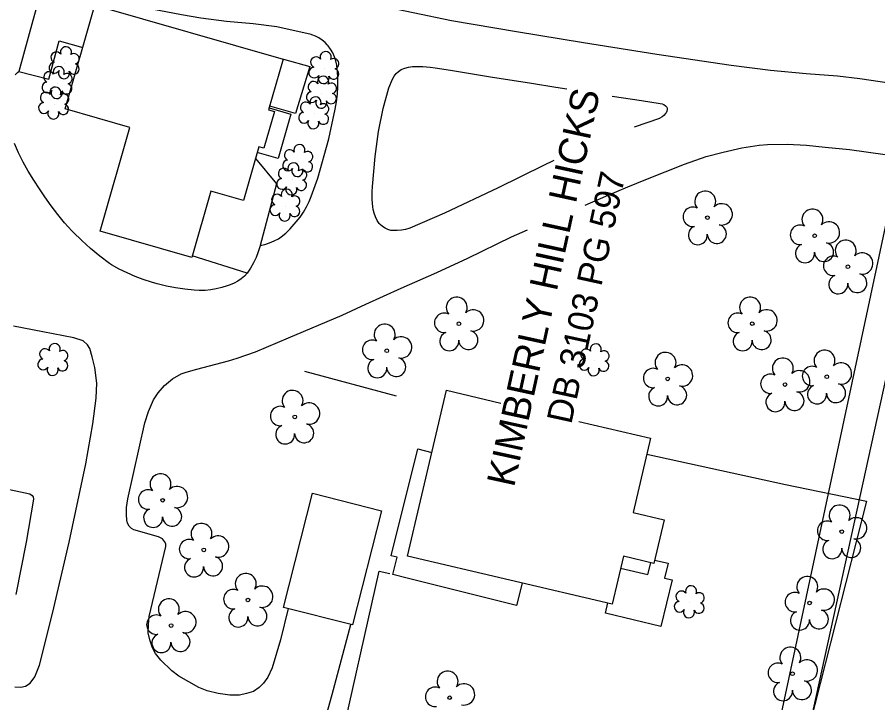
# Model space of a CAD drawing. Extents: x 1611576 to 1617186, y 899279 to 905462.
# Drawn here: x 1616359.3 to 1616512.4, y 901237.8 to 901359.7 of the extents above; entities that cross this region are included whole.
import ezdxf

# ---------------------------------------------------------------- set-up
doc = ezdxf.new("R2010")
doc.units = 0
for name, color, linetype in [('Exist Building', 7, 'Continuous'), ('Exist Building Metal Canopy', 7, 'Continuous'), ('Exist Other Culture Area Outline', 7, 'Continuous'), ('Exist Other Culture Fence Line', 7, 'Continuous'), ('Exist Property Deed Book Text', 7, 'Continuous'), ('Exist Property Owner Text', 7, 'Continuous'), ('Exist Roads Soil', 7, 'Continuous'), ('Exist Vegetation Shrub CELL', 7, 'Continuous'), ('Exist Vegetation Tree CELL', 7, 'Continuous'), ('Prop 6 In Gas Line (B2)', 7, 'Continuous'), ('Prop OH Pow Tel CATV Lines', 7, 'Continuous')]:
    doc.layers.add(name, color=color, linetype=linetype)

msp = doc.modelspace()

# ---------------------------------------------------------------- linework, layer by layer
at = {"layer": 'Exist Building'}
msp.add_lwpolyline([(1616367.84, 901343.41), (1616373.15, 901361.89), (1616406.65, 901352.27), (1616404.06, 901343.26), (1616405.09, 901342.96), (1616403.21, 901336.42), (1616402.31, 901336.68), (1616399.57, 901327.14), (1616393.78, 901328.81), (1616390.39, 901317), (1616374.07, 901321.69), (1616379.36, 901340.1)], close=True, dxfattribs=at)
msp.add_lwpolyline([(1616459.25, 901287.84), (1616472.01, 901284.86), (1616468.9, 901271.6), (1616474.4, 901270.32), (1616472.58, 901262.57), (1616467.17, 901263.84), (1616465.19, 901255.34), (1616428.78, 901263.86), (1616435.68, 901293.36), (1616445.35, 901291.1)], dxfattribs=at)
at = {"layer": 'Exist Building Metal Canopy'}
msp.add_lwpolyline([(1616424.14, 901271.94), (1616419, 901251.63), (1616406.73, 901254.74), (1616411.87, 901275.05)], close=True, dxfattribs=at)
at = {"layer": 'Exist Other Culture Area Outline'}
for points in [[(1616374.23, 901361.58), (1616374.63, 901362.94), (1616374.66, 901363.02), (1616369.34, 901364.47), (1616364, 901365.94), (1616362.13, 901359.12), (1616359.6, 901350.09), (1616364.93, 901348.68), (1616366.82, 901355.52), (1616370.98, 901354.34)], [(1616406.69, 901352.27), (1616411.36, 901350.93), (1616408.86, 901342.62), (1616404.25, 901343.93)], [(1616404.15, 901343.58), (1616408, 901342.49), (1616405.75, 901334.6), (1616402.02, 901335.66)], [(1616401.71, 901334.58), (1616405.43, 901330.11), (1616402.56, 901319.1), (1616402.54, 901319.04), (1616402.22, 901318), (1616401.83, 901316.99), (1616401.36, 901316.01), (1616400.82, 901315.06), (1616400.25, 901314.21), (1616390.46, 901317.25)], [(1616449.19, 901259.08), (1616448.18, 901255.06), (1616428.71, 901259.95), (1616426.16, 901260.6), (1616426.92, 901263.65), (1616425.84, 901263.92), (1616430.62, 901282.94), (1616433.09, 901282.31)], [(1616472.72, 901263.17), (1616475.12, 901262.59), (1616474.49, 901259.95), (1616475.82, 901259.63), (1616473.85, 901251.35), (1616463.96, 901253.71), (1616464.39, 901255.53)], [(1616466.68, 901261.73), (1616471.52, 901260.58), (1616472.03, 901262.7)]]:
    msp.add_lwpolyline(points, dxfattribs=at)
at = {"layer": 'Exist Other Culture Fence Line'}
msp.add_line((1616426.82, 901292.33), (1616410.48, 901296.69), dxfattribs=at)
msp.add_lwpolyline([(1616471.34, 901282), (1616496, 901276.61), (1616510.44, 901273.65), (1616499.39, 901230.25), (1616492.71, 901200.51), (1616464, 901211.34), (1616431.25, 901223.21), (1616416.45, 901228.69), (1616423.75, 901261.2), (1616425.59, 901260.77)], dxfattribs=at)
at = {"layer": 'Exist Roads Soil'}
for points in [[(1616414.1, 901355.23), (1616413.58, 901355.67), (1616413.01, 901356.05), (1616412.39, 901356.37), (1616411.75, 901356.6), (1616411.62, 901356.64), (1616405.52, 901358), (1616401.33, 901358.52), (1616396.57, 901358.97), (1616392.02, 901359.55), (1616388.53, 901360.13), (1616383.27, 901361.16), (1616374.66, 901363.02)], [(1616523.33, 901346.48), (1616519.44, 901347.01), (1616514.46, 901347.97), (1616509.21, 901348.79), (1616505.25, 901349.23), (1616499.66, 901349.68), (1616493.34, 901350.26), (1616486.34, 901351.16), (1616473.14, 901353.09), (1616460.08, 901355.19), (1616448.14, 901357.11), (1616436.59, 901359.1), (1616422.94, 901361.95)], [(1616402.56, 901319.1), (1616403.41, 901319.3), (1616404.24, 901319.57), (1616405.05, 901319.92), (1616405.82, 901320.33), (1616406.27, 901320.63), (1616407.11, 901321.32), (1616407.9, 901322.08), (1616408.63, 901322.89), (1616408.96, 901323.31), (1616409.64, 901324.15), (1616410.25, 901325.04), (1616410.79, 901325.98), (1616411.26, 901326.95), (1616411.61, 901327.82), (1616412.8, 901331.1), (1616414.78, 901338.12), (1616415.88, 901343.34), (1616416.12, 901344.69), (1616416.28, 901346.06), (1616416.36, 901347.43), (1616416.36, 901348.8), (1616416.28, 901350.17), (1616416.25, 901350.47), (1616416.17, 901351.22), (1616416.01, 901351.96), (1616415.77, 901352.68), (1616415.46, 901353.37), (1616415.07, 901354.02), (1616414.63, 901354.63), (1616414.47, 901354.82), (1616414.1, 901355.23)], [(1616358.96, 901349.45), (1616359.41, 901349.92), (1616359.6, 901350.09)], [(1616454.8, 901334.26), (1616452.93, 901333.37), (1616444.91, 901329.39), (1616435.34, 901324.88), (1616429.16, 901322.21), (1616428.43, 901321.98), (1616427.69, 901321.84), (1616426.94, 901321.77), (1616426.18, 901321.78), (1616425.81, 901321.81), (1616425.29, 901321.96), (1616424.79, 901322.19), (1616424.33, 901322.48), (1616423.92, 901322.84), (1616423.75, 901323.03), (1616423.37, 901323.59), (1616423.06, 901324.2), (1616422.82, 901324.84), (1616422.66, 901325.5), (1616422.59, 901325.99), (1616422.5, 901327.31), (1616422.49, 901328.64), (1616422.53, 901329.59), (1616423.01, 901334.96), (1616423.59, 901339.4), (1616424.42, 901343.5), (1616425.44, 901347.16), (1616426.07, 901348.73), (1616426.37, 901349.23), (1616426.74, 901349.69), (1616427.17, 901350.09), (1616427.65, 901350.43), (1616427.66, 901350.43), (1616428.3, 901350.68), (1616428.96, 901350.85), (1616429.63, 901350.94), (1616430.16, 901350.95), (1616431.47, 901350.94), (1616432.78, 901350.84), (1616433.69, 901350.74), (1616436.39, 901350.3), (1616443.55, 901349.11), (1616450.81, 901347.99), (1616455.14, 901347.3), (1616457.08, 901346.99)], [(1616465.2, 901345.71), (1616470.38, 901344.91), (1616473.74, 901344.37), (1616474.08, 901344.31), (1616474.39, 901344.17), (1616474.66, 901343.96), (1616474.88, 901343.7), (1616474.94, 901343.61), (1616474.96, 901343.31), (1616474.91, 901343.01), (1616474.78, 901342.74), (1616474.65, 901342.57), (1616474.38, 901342.24), (1616474.05, 901341.98), (1616473.68, 901341.77), (1616473.57, 901341.73), (1616469.1, 901340.19)], [(1616400.25, 901314.21), (1616399.74, 901313.67), (1616399.18, 901313.18), (1616398.57, 901312.76), (1616397.91, 901312.4), (1616397.23, 901312.12), (1616396.69, 901311.95), (1616395.73, 901311.63), (1616394.74, 901311.38), (1616393.75, 901311.22), (1616392.74, 901311.13), (1616391.72, 901311.11), (1616390.82, 901311.17), (1616389.16, 901311.34), (1616387.5, 901311.58), (1616385.86, 901311.91), (1616384.23, 901312.31), (1616383.25, 901312.59), (1616381.76, 901313.06), (1616380.3, 901313.61), (1616378.87, 901314.23), (1616377.47, 901314.92), (1616376.11, 901315.69), (1616375.72, 901315.92), (1616374.03, 901317.23), (1616372.39, 901318.6), (1616370.81, 901320.02), (1616369.28, 901321.51), (1616369.06, 901321.73), (1616367.77, 901323.16), (1616366.54, 901324.64), (1616365.37, 901326.17), (1616364.26, 901327.75), (1616363.31, 901329.22), (1616362.27, 901330.76), (1616361.3, 901332.33), (1616360.4, 901333.95), (1616359.57, 901335.61), (1616358.82, 901337.28)], [(1616460.38, 901326.31), (1616464.07, 901327.91), (1616467.97, 901329.54), (1616471.15, 901330.85), (1616474.63, 901332.24), (1616478.05, 901333.56), (1616481.89, 901334.93), (1616484.93, 901335.73), (1616488.23, 901336.48), (1616491.34, 901336.98), (1616492.83, 901337.1), (1616496.3, 901337.13), (1616499.77, 901336.95), (1616503.08, 901336.62), (1616507.42, 901336.19), (1616513.71, 901335.32), (1616521.24, 901334.36), (1616526.1, 901333.58), (1616527.83, 901333.25)], [(1616407.54, 901254.53), (1616406.15, 901248.98), (1616404.67, 901244.01), (1616403.89, 901242.32), (1616403.13, 901241.28), (1616402.36, 901240.47), (1616401.37, 901239.8), (1616400.1, 901239.4), (1616398.85, 901239.14), (1616397.16, 901239.14), (1616395.1, 901239.4), (1616393.13, 901239.91), (1616391.62, 901240.5), (1616388.1, 901242.5), (1616386.83, 901243.43), (1616384.87, 901245.36), (1616383.96, 901246.53), (1616383.38, 901247.55), (1616382.91, 901248.99), (1616382.65, 901250.24), (1616382.69, 901251.63), (1616382.8, 901253.12), (1616385.79, 901265.58), (1616385.78, 901266.04), (1616385.55, 901266.44), (1616385.19, 901266.95), (1616384.44, 901267.32), (1616380.1, 901268.57), (1616379.68, 901268.76), (1616379.25, 901269.21), (1616378.95, 901269.73), (1616378.81, 901270.25), (1616378.76, 901271.27), (1616378.8, 901272.52), (1616379, 901274.04), (1616382.01, 901287.55), (1616382.67, 901289.61), (1616383.58, 901291.65), (1616384.38, 901292.9), (1616385.54, 901294.22), (1616386.93, 901295.41), (1616388.47, 901296.27), (1616389.38, 901296.61), (1616391.3, 901297.13), (1616396.9, 901298.58), (1616398.49, 901299.09), (1616401.73, 901300.22), (1616407.58, 901302.67), (1616417.13, 901306.74), (1616421.36, 901308.68), (1616427.64, 901311.52), (1616434.01, 901314.31), (1616439.51, 901316.87), (1616447.26, 901320.66), (1616450.1, 901321.88)], [(1616358.9, 901240.59), (1616359.98, 901240.58), (1616360.8, 901240.75), (1616361.61, 901241.29), (1616362.45, 901242.4), (1616363.31, 901244.47), (1616365.63, 901253.68), (1616368.57, 901266.32), (1616371.53, 901280.27), (1616372.78, 901287.41), (1616373.39, 901291.98), (1616373.48, 901294.61), (1616373.12, 901297.4), (1616372.69, 901299.29), (1616372.26, 901300.78), (1616371.83, 901301.47), (1616371.07, 901302.14), (1616369.38, 901302.71), (1616363.86, 901303.77), (1616358.67, 901304.74)], [(1616356.26, 901276.1), (1616361.56, 901274.96), (1616362.01, 901274.64), (1616362.17, 901274.39), (1616362.24, 901273.97), (1616360.9, 901266.34), (1616359.06, 901257.05)], [(1616414.12, 901215.18), (1616412.83, 901217.9), (1616412.15, 901219.81), (1616411.78, 901221.85), (1616411.63, 901223.98), (1616411.68, 901225.43), (1616412.07, 901227.54), (1616415.38, 901239.26), (1616418.68, 901251.71)]]:
    msp.add_lwpolyline(points, dxfattribs=at)
at = {"layer": 'Exist Vegetation Shrub CELL'}
for p, q in [((1616367.77, 901351.45), (1616367.77, 901351.45)), ((1616413.97, 901350.58), (1616413.97, 901350.58)), ((1616366.49, 901347.93), (1616366.49, 901347.93)), ((1616413.53, 901346.2), (1616413.53, 901346.2)), ((1616365.89, 901344.28), (1616365.89, 901344.28)), ((1616412.16, 901342.54), (1616412.16, 901342.54)), ((1616409.31, 901334.05), (1616409.31, 901334.05)), ((1616408.24, 901330.78), (1616408.24, 901330.78)), ((1616407.04, 901326.13), (1616407.04, 901326.13)), ((1616365.76, 901298.66), (1616365.76, 901298.66)), ((1616462.03, 901298.6), (1616462.03, 901298.6)), ((1616478.97, 901255.56), (1616478.97, 901255.56))]:
    msp.add_line(p, q, dxfattribs=at)
for centre, radius, start, end in [((1616366.29, 901352.58), 0.968, 35.8908, 245.4216), ((1616368, 901353.49), 0.99, 334.8391, 200.4717), ((1616369.44, 901352.32), 0.929, 284.4567, 126.0861), ((1616414.2, 901352.62), 0.99, 334.8391, 200.4717), ((1616365.97, 901350.75), 0.955, 95.1099, 327.9534), ((1616412.49, 901351.71), 0.968, 35.8908, 245.4216), ((1616415.64, 901351.45), 0.929, 284.4567, 126.0861), ((1616365.01, 901349.05), 0.968, 35.8908, 245.4216), ((1616366.72, 901349.97), 0.99, 334.8391, 200.4717), ((1616367.64, 901349.77), 0.984, 151.2797, 21.387), ((1616369.41, 901350.52), 0.937, 204.9913, 73.4601), ((1616412.17, 901349.88), 0.955, 95.1099, 327.9534), ((1616415.61, 901349.65), 0.937, 204.9913, 73.4601), ((1616368.16, 901348.8), 0.929, 284.4567, 126.0861), ((1616413.76, 901348.24), 0.99, 334.8391, 200.4717), ((1616413.84, 901348.9), 0.984, 151.2797, 21.387), ((1616364.69, 901347.22), 0.955, 95.1099, 327.9534), ((1616366.12, 901346.32), 0.99, 334.8391, 200.4717), ((1616368.13, 901347), 0.937, 204.9913, 73.4601), ((1616412.05, 901347.33), 0.968, 35.8908, 245.4216), ((1616415.21, 901347.07), 0.929, 284.4567, 126.0861), ((1616364.41, 901345.41), 0.968, 35.8908, 245.4216), ((1616366.36, 901346.24), 0.984, 151.2797, 21.387), ((1616367.57, 901345.15), 0.929, 284.4567, 126.0861), ((1616411.73, 901345.5), 0.955, 95.1099, 327.9534), ((1616412.39, 901344.58), 0.99, 334.8391, 200.4717), ((1616415.17, 901345.27), 0.937, 204.9913, 73.4601), ((1616364.09, 901343.58), 0.955, 95.1099, 327.9534), ((1616367.53, 901343.35), 0.937, 204.9913, 73.4601), ((1616410.68, 901343.67), 0.968, 35.8908, 245.4216), ((1616413.41, 901344.52), 0.984, 151.2797, 21.387), ((1616413.83, 901343.41), 0.929, 284.4567, 126.0861), ((1616365.77, 901342.6), 0.984, 151.2797, 21.387), ((1616410.36, 901341.84), 0.955, 95.1099, 327.9534), ((1616413.8, 901341.61), 0.937, 204.9913, 73.4601), ((1616412.03, 901340.86), 0.984, 151.2797, 21.387), ((1616409.54, 901336.09), 0.99, 334.8391, 200.4717), ((1616407.83, 901335.18), 0.968, 35.8908, 245.4216), ((1616410.98, 901334.92), 0.929, 284.4567, 126.0861), ((1616407.51, 901333.35), 0.955, 95.1099, 327.9534), ((1616408.47, 901332.82), 0.99, 334.8391, 200.4717), ((1616410.95, 901333.12), 0.937, 204.9913, 73.4601), ((1616406.75, 901331.91), 0.968, 35.8908, 245.4216), ((1616409.18, 901332.37), 0.984, 151.2797, 21.387), ((1616409.91, 901331.65), 0.929, 284.4567, 126.0861), ((1616406.44, 901330.07), 0.955, 95.1099, 327.9534), ((1616409.87, 901329.85), 0.937, 204.9913, 73.4601), ((1616407.27, 901328.17), 0.99, 334.8391, 200.4717), ((1616408.11, 901329.09), 0.984, 151.2797, 21.387), ((1616405.56, 901327.26), 0.968, 35.8908, 245.4216), ((1616408.71, 901327), 0.929, 284.4567, 126.0861), ((1616405.24, 901325.43), 0.955, 95.1099, 327.9534), ((1616408.68, 901325.2), 0.937, 204.9913, 73.4601), ((1616406.91, 901324.45), 0.984, 151.2797, 21.387), ((1616365.99, 901300.7), 0.99, 334.8391, 200.4717), ((1616462.26, 901300.64), 0.99, 334.8391, 200.4717), ((1616364.28, 901299.79), 0.968, 35.8908, 245.4216), ((1616367.43, 901299.53), 0.929, 284.4567, 126.0861), ((1616460.54, 901299.73), 0.968, 35.8908, 245.4216), ((1616463.7, 901299.47), 0.929, 284.4567, 126.0861), ((1616363.96, 901297.96), 0.955, 95.1099, 327.9534), ((1616367.4, 901297.74), 0.937, 204.9913, 73.4601), ((1616460.23, 901297.9), 0.955, 95.1099, 327.9534), ((1616463.66, 901297.67), 0.937, 204.9913, 73.4601), ((1616365.63, 901296.98), 0.984, 151.2797, 21.387), ((1616461.9, 901296.92), 0.984, 151.2797, 21.387), ((1616479.2, 901257.6), 0.99, 334.8391, 200.4717), ((1616477.48, 901256.69), 0.968, 35.8908, 245.4216), ((1616480.64, 901256.43), 0.929, 284.4567, 126.0861), ((1616477.17, 901254.86), 0.955, 95.1099, 327.9534), ((1616480.6, 901254.63), 0.937, 204.9913, 73.4601), ((1616478.84, 901253.88), 0.984, 151.2797, 21.387)]:
    msp.add_arc(centre, radius, start, end, dxfattribs=at)
at = {"layer": 'Exist Vegetation Tree CELL'}
for p, q in [((1616482.11, 901324.07), (1616482.11, 901324.07)), ((1616501.19, 901320.85), (1616501.19, 901320.85)), ((1616507.11, 901315.33), (1616507.11, 901315.33)), ((1616437.9, 901305.2), (1616437.9, 901305.2)), ((1616490.09, 901305.21), (1616490.09, 901305.21)), ((1616425.08, 901300.4), (1616425.08, 901300.4)), ((1616475.05, 901295.39), (1616475.05, 901295.39)), ((1616503.34, 901295.76), (1616503.34, 901295.76)), ((1616495.92, 901294.37), (1616495.92, 901294.37)), ((1616408.7, 901288.62), (1616408.7, 901288.62)), ((1616385.21, 901273.79), (1616385.21, 901273.79)), ((1616506.02, 901268.22), (1616506.02, 901268.22)), ((1616392.51, 901264.97), (1616392.51, 901264.97)), ((1616400.37, 901256.06), (1616400.37, 901256.06)), ((1616500.28, 901255.53), (1616500.28, 901255.53)), ((1616386.7, 901251.51), (1616386.7, 901251.51)), ((1616497.26, 901242.94), (1616497.26, 901242.94)), ((1616436.27, 901238.68), (1616436.27, 901238.68))]:
    msp.add_line(p, q, dxfattribs=at)
for centre in [(1616482.11, 901324.07), (1616501.19, 901320.85), (1616507.11, 901315.33), (1616437.9, 901305.2), (1616490.09, 901305.21), (1616425.08, 901300.4), (1616475.05, 901295.39), (1616503.34, 901295.76), (1616495.92, 901294.37), (1616408.7, 901288.62), (1616385.21, 901273.79), (1616506.02, 901268.22), (1616392.51, 901264.97), (1616400.37, 901256.06), (1616500.28, 901255.53), (1616386.7, 901251.51), (1616497.26, 901242.94), (1616436.27, 901238.68)]:
    msp.add_circle(centre, 0.326, dxfattribs=at)
for centre, radius, start, end in [((1616481.73, 901326.95), 1.86, 330.1651, 219.7134), ((1616479.51, 901324.23), 1.73, 62.6636, 279.3457), ((1616484.66, 901324.66), 1.9, 257.1011, 134.1999), ((1616500.8, 901323.73), 1.86, 330.1651, 219.7134), ((1616480.41, 901320.95), 1.69, 111.5671, 6.231), ((1616483.79, 901321.17), 1.7, 181.2822, 74.56), ((1616498.58, 901321.01), 1.73, 62.6636, 279.3457), ((1616503.74, 901321.44), 1.9, 257.1011, 134.1999), ((1616502.86, 901317.95), 1.7, 181.2822, 74.56), ((1616506.72, 901318.21), 1.86, 330.1651, 219.7134), ((1616499.48, 901317.73), 1.69, 111.5671, 6.231), ((1616504.5, 901315.49), 1.73, 62.6636, 279.3457), ((1616509.65, 901315.92), 1.9, 257.1011, 134.1999), ((1616505.4, 901312.21), 1.69, 111.5671, 6.231), ((1616508.78, 901312.43), 1.7, 181.2822, 74.56), ((1616437.52, 901308.08), 1.86, 330.1651, 219.7134), ((1616489.71, 901308.08), 1.86, 330.1651, 219.7134), ((1616440.45, 901305.79), 1.9, 257.1011, 134.1999), ((1616492.64, 901305.8), 1.9, 257.1011, 134.1999), ((1616435.3, 901305.36), 1.73, 62.6636, 279.3457), ((1616487.49, 901305.36), 1.73, 62.6636, 279.3457), ((1616424.7, 901303.28), 1.86, 330.1651, 219.7134), ((1616427.63, 901300.99), 1.9, 257.1011, 134.1999), ((1616436.2, 901302.08), 1.69, 111.5671, 6.231), ((1616439.58, 901302.3), 1.7, 181.2822, 74.56), ((1616488.39, 901302.09), 1.69, 111.5671, 6.231), ((1616491.76, 901302.31), 1.7, 181.2822, 74.56), ((1616422.48, 901300.56), 1.73, 62.6636, 279.3457), ((1616474.67, 901298.26), 1.86, 330.1651, 219.7134), ((1616502.95, 901298.63), 1.86, 330.1651, 219.7134), ((1616423.38, 901297.28), 1.69, 111.5671, 6.231), ((1616426.75, 901297.5), 1.7, 181.2822, 74.56), ((1616495.54, 901297.25), 1.86, 330.1651, 219.7134), ((1616505.88, 901296.35), 1.9, 257.1011, 134.1999), ((1616472.45, 901295.54), 1.73, 62.6636, 279.3457), ((1616477.6, 901295.98), 1.9, 257.1011, 134.1999), ((1616498.47, 901294.96), 1.9, 257.1011, 134.1999), ((1616500.73, 901295.91), 1.73, 62.6636, 279.3457), ((1616493.32, 901294.53), 1.73, 62.6636, 279.3457), ((1616408.32, 901291.5), 1.86, 330.1651, 219.7134), ((1616473.35, 901292.27), 1.69, 111.5671, 6.231), ((1616476.73, 901292.49), 1.7, 181.2822, 74.56), ((1616501.63, 901292.64), 1.69, 111.5671, 6.231), ((1616505.01, 901292.86), 1.7, 181.2822, 74.56), ((1616494.22, 901291.25), 1.69, 111.5671, 6.231), ((1616497.6, 901291.47), 1.7, 181.2822, 74.56), ((1616406.1, 901288.78), 1.73, 62.6636, 279.3457), ((1616411.25, 901289.21), 1.9, 257.1011, 134.1999), ((1616410.38, 901285.73), 1.7, 181.2822, 74.56), ((1616407, 901285.5), 1.69, 111.5671, 6.231), ((1616384.83, 901276.66), 1.86, 330.1651, 219.7134), ((1616382.61, 901273.94), 1.73, 62.6636, 279.3457), ((1616387.76, 901274.37), 1.9, 257.1011, 134.1999), ((1616383.51, 901270.66), 1.69, 111.5671, 6.231), ((1616386.89, 901270.89), 1.7, 181.2822, 74.56), ((1616505.64, 901271.1), 1.86, 330.1651, 219.7134), ((1616508.57, 901268.81), 1.9, 257.1011, 134.1999), ((1616392.12, 901267.84), 1.86, 330.1651, 219.7134), ((1616503.42, 901268.38), 1.73, 62.6636, 279.3457), ((1616395.06, 901265.56), 1.9, 257.1011, 134.1999), ((1616389.9, 901265.12), 1.73, 62.6636, 279.3457), ((1616504.32, 901265.1), 1.69, 111.5671, 6.231), ((1616507.7, 901265.33), 1.7, 181.2822, 74.56), ((1616390.8, 901261.85), 1.69, 111.5671, 6.231), ((1616394.18, 901262.07), 1.7, 181.2822, 74.56), ((1616399.99, 901258.93), 1.86, 330.1651, 219.7134), ((1616499.89, 901258.4), 1.86, 330.1651, 219.7134), ((1616402.92, 901256.65), 1.9, 257.1011, 134.1999), ((1616397.77, 901256.21), 1.73, 62.6636, 279.3457), ((1616497.67, 901255.68), 1.73, 62.6636, 279.3457), ((1616502.83, 901256.12), 1.9, 257.1011, 134.1999), ((1616386.31, 901254.39), 1.86, 330.1651, 219.7134), ((1616389.25, 901252.1), 1.9, 257.1011, 134.1999), ((1616398.67, 901252.94), 1.69, 111.5671, 6.231), ((1616402.05, 901253.16), 1.7, 181.2822, 74.56), ((1616498.57, 901252.41), 1.69, 111.5671, 6.231), ((1616501.95, 901252.63), 1.7, 181.2822, 74.56), ((1616384.09, 901251.67), 1.73, 62.6636, 279.3457), ((1616384.99, 901248.39), 1.69, 111.5671, 6.231), ((1616388.37, 901248.61), 1.7, 181.2822, 74.56), ((1616496.87, 901245.82), 1.86, 330.1651, 219.7134), ((1616494.65, 901243.1), 1.73, 62.6636, 279.3457), ((1616499.81, 901243.53), 1.9, 257.1011, 134.1999), ((1616435.89, 901241.55), 1.86, 330.1651, 219.7134), ((1616495.56, 901239.82), 1.69, 111.5671, 6.231), ((1616498.93, 901240.04), 1.7, 181.2822, 74.56), ((1616433.67, 901238.83), 1.73, 62.6636, 279.3457), ((1616438.82, 901239.27), 1.9, 257.1011, 134.1999)]:
    msp.add_arc(centre, radius, start, end, dxfattribs=at)
at = {"layer": 'Prop 6 In Gas Line (B2)'}
msp.add_line((1616442.17, 900967.71), (1616564.88, 901528.63), dxfattribs=at)
at = {"layer": 'Prop OH Pow Tel CATV Lines'}
msp.add_line((1616494.69, 901233.15), (1616522.09, 901361.37), dxfattribs=at)

# ---------------------------------------------------------------- texts
at = {"layer": 'Exist Property Deed Book Text'}
msp.add_text('DB 3103 PG 597', height=4.5, rotation=77.7167, dxfattribs=at).set_placement((1616457.89, 901287.19))
at = {"layer": 'Exist Property Owner Text'}
msp.add_text('KIMBERLY HILL HICKS', height=5, rotation=77.7167, dxfattribs=at).set_placement((1616447.71, 901275.97))

doc.saveas('drawing.dxf')
